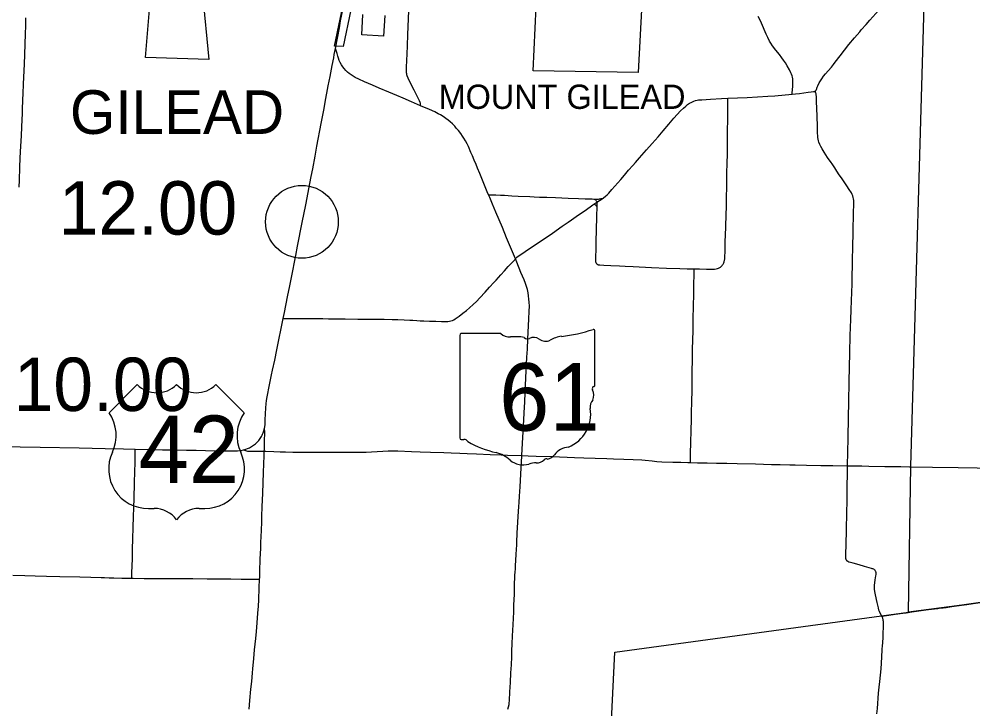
# Model space of a CAD drawing. Extents: x 1815539 to 1947826, y 273303 to 993194.
# Drawn here: x 1869978 to 1889640, y 911339 to 925558 of the extents above; entities that cross this region are included whole.
import ezdxf

# ---------------------------------------------------------------- set-up
doc = ezdxf.new("R2010")
doc.units = 0
for name, color, linetype in [('Default', 7, 'Continuous'), ('GM_X_Corporation', 7, 'Continuous'), ('GM_X_Corporation_Text', 7, 'Continuous'), ('GM_X_County_Road', 7, 'Continuous'), ('GM_X_State_Route', 7, 'Continuous'), ('GM_X_Township', 7, 'Continuous'), ('GM_X_Township_Road', 7, 'Continuous'), ('GM_X_Township_Text', 7, 'Continuous'), ('GM_X_US_Route', 7, 'Continuous'), ('PV_X_Shoulder', 7, 'Continuous'), ('SC_Shading3', 7, 'Continuous')]:
    doc.layers.add(name, color=color, linetype=linetype)

msp = doc.modelspace()

# ---------------------------------------------------------------- linework, layer by layer
at = {"layer": 'Default'}
msp.add_circle((1875809, 921379), 750, dxfattribs=at)
at = {"layer": 'GM_X_Corporation'}
for points in [[(1882818, 925881), (1882743, 924455), (1880574, 924491), (1880657, 926260)], [(1873757, 926076), (1873892, 924723), (1872581, 924769), (1872681, 925920)], [(1876816, 925750), (1876660, 924993), (1876483, 925000), (1876685, 925989)], [(1877517, 925630), (1877493, 925208), (1877045, 925233), (1877061, 925652)]]:
    msp.add_lwpolyline(points, dxfattribs=at)
at = {"layer": 'GM_X_County_Road'}
for points in [[(1878254, 923773), (1878254, 923791), (1878253, 923809), (1878251, 923824), (1878245, 923840), (1878232, 923870), (1878190, 923956), (1878123, 924092), (1878042, 924254), (1878000, 924342), (1877981, 924388), (1877972, 924412), (1877968, 924430), (1877965, 924450), (1877963, 924466), (1877962, 924499), (1877965, 924564), (1877977, 924843), (1877984, 925008), (1877992, 925238), (1878010, 925731), (1878016, 925917)], [(1875032, 916651), (1875034, 916687), (1875040, 916867), (1875045, 917030), (1875044, 917049), (1875041, 917073), (1875035, 917100), (1875033, 917111)], [(1874936, 914014), (1874938, 914048), (1874941, 914179), (1874951, 914424), (1874959, 914654), (1874965, 914769), (1874973, 915014), (1874979, 915195), (1874985, 915309), (1874992, 915506), (1875003, 915785), (1875010, 915998), (1875017, 916211), (1875023, 916392), (1875029, 916556), (1875032, 916651)], [(1880340, 916562), (1880475, 916559), (1880639, 916552), (1880967, 916540), (1881425, 916524), (1881622, 916518), (1881851, 916511), (1882097, 916501), (1882228, 916496), (1882441, 916490), (1882638, 916482), (1882818, 916474), (1882883, 916468), (1883029, 916451), (1883127, 916441), (1883226, 916434), (1883455, 916428), (1883619, 916425), (1883767, 916420), (1883819, 916419)], [(1883819, 916419), (1883963, 916415), (1884160, 916411), (1884357, 916406), (1884570, 916402), (1884783, 916396), (1885160, 916388), (1885488, 916380), (1885668, 916375), (1885864, 916371), (1885979, 916369), (1886209, 916366), (1886504, 916360), (1886750, 916358), (1887055, 916352)], [(1887765, 913249), (1887727, 913315), (1887714, 913344), (1887704, 913375), (1887691, 913422), (1887665, 913534), (1887630, 913694), (1887619, 913759), (1887613, 913807), (1887611, 913840), (1887613, 913888), (1887618, 913937), (1887628, 914002), (1887642, 914083), (1887645, 914109), (1887645, 914116), (1887646, 914123), (1887646, 914133), (1887645, 914141), (1887644, 914150), (1887642, 914158), (1887640, 914167), (1887636, 914175), (1887632, 914182), (1887627, 914190), (1887622, 914196), (1887616, 914202), (1887609, 914207), (1887602, 914212), (1887595, 914217), (1887580, 914224), (1887564, 914230), (1887548, 914235), (1887406, 914276), (1887295, 914306), (1887169, 914341), (1887090, 914365), (1887084, 914367), (1887075, 914371), (1887068, 914375), (1887061, 914378), (1887055, 914382), (1887049, 914387), (1887044, 914392), (1887038, 914398), (1887034, 914404), (1887030, 914411), (1887027, 914417), (1887024, 914426), (1887022, 914432), (1887021, 914441), (1887019, 914449), (1887019, 914457), (1887018, 914489), (1887021, 914555), (1887026, 914702), (1887028, 914801), (1887028, 914817), (1887031, 914931), (1887035, 915078), (1887039, 915341), (1887046, 915669), (1887051, 915866), (1887058, 916244), (1887055, 916352)], [(1869852, 914094), (1870098, 914088), (1870311, 914082), (1870541, 914077), (1870820, 914070), (1871230, 914060), (1871459, 914053), (1871672, 914048), (1871738, 914046), (1871836, 914044), (1871934, 914041), (1872098, 914036), (1872301, 914032)], [(1872301, 914032), (1872328, 914032), (1872557, 914029), (1872754, 914028), (1872902, 914026), (1872984, 914025), (1873164, 914026), (1873377, 914026), (1873558, 914025), (1873853, 914022), (1874083, 914021), (1874345, 914019), (1874559, 914017), (1874755, 914017), (1874903, 914015), (1874936, 914014)], [(1874719, 911335), (1874736, 911514), (1874757, 911743), (1874773, 911907), (1874789, 912086), (1874796, 912168), (1874817, 912380), (1874834, 912560), (1874858, 912788), (1874871, 912935), (1874887, 913115), (1874903, 913311), (1874912, 913459), (1874918, 913590), (1874929, 913835), (1874936, 914014)], [(1887662, 911236), (1887671, 911350), (1887696, 911661), (1887708, 911791), (1887721, 911905), (1887735, 912036), (1887746, 912166), (1887754, 912281), (1887763, 912412), (1887770, 912557), (1887777, 912655), (1887780, 912687), (1887787, 912833), (1887793, 912931), (1887797, 912996), (1887800, 913061), (1887800, 913094), (1887798, 913127), (1887795, 913144), (1887792, 913160), (1887789, 913177), (1887781, 913208), (1887777, 913221), (1887775, 913228), (1887771, 913238), (1887765, 913249)]]:
    msp.add_lwpolyline(points, dxfattribs=at)
at = {"layer": 'GM_X_State_Route'}
for points in [[(1880340, 916567), (1880381, 917295), (1880389, 917442), (1880403, 917672), (1880413, 917852), (1880427, 918163), (1880448, 918589), (1880456, 918753), (1880467, 918966), (1880489, 919375), (1880495, 919539), (1880497, 919638), (1880494, 919720), (1880489, 919786), (1880481, 919851), (1880470, 919916), (1880456, 919981), (1880443, 920028), (1880416, 920106), (1880387, 920183), (1880324, 920335), (1880238, 920547), (1880209, 920616), (1880167, 920714), (1880029, 921047), (1879940, 921259), (1879808, 921577), (1879736, 921741), (1879680, 921879), (1879656, 921938), (1879630, 922000), (1879561, 922166), (1879473, 922378), (1879428, 922484), (1879398, 922560), (1879361, 922651), (1879322, 922740), (1879316, 922754), (1879303, 922782), (1879291, 922810), (1879239, 922929), (1879212, 922988), (1879182, 923047), (1879148, 923104), (1879121, 923145), (1879083, 923198), (1879033, 923263), (1878991, 923313), (1878958, 923350), (1878911, 923396), (1878863, 923440), (1878825, 923472), (1878772, 923512), (1878718, 923549), (1878662, 923584), (1878619, 923608), (1878546, 923645), (1878441, 923693), (1878254, 923773), (1878064, 923855), (1877898, 923925), (1877763, 923984), (1877597, 924054), (1877400, 924136), (1877265, 924195), (1877100, 924266), (1876980, 924320), (1876907, 924355), (1876864, 924379), (1876823, 924406), (1876784, 924435), (1876747, 924467), (1876712, 924501), (1876680, 924538), (1876650, 924576), (1876623, 924617), (1876599, 924660), (1876579, 924704), (1876562, 924750), (1876547, 924797), (1876534, 924847), (1876499, 924955)], [(1880055, 911332), (1880068, 911380), (1880079, 911428), (1880083, 911461), (1880087, 911510), (1880095, 911690), (1880107, 911887), (1880117, 912084), (1880126, 912247), (1880133, 912411), (1880136, 912510), (1880144, 912706), (1880148, 912821), (1880156, 912985), (1880160, 913050), (1880169, 913230), (1880174, 913311), (1880177, 913377), (1880180, 913475), (1880188, 913705), (1880192, 913885), (1880193, 913934), (1880193, 913966), (1880195, 913998), (1880197, 914047), (1880200, 914096), (1880205, 914160), (1880209, 914226), (1880213, 914307), (1880218, 914388), (1880221, 914437), (1880224, 914486), (1880226, 914535), (1880231, 914616), (1880237, 914731), (1880240, 914780), (1880242, 914845), (1880245, 914894), (1880248, 914959), (1880262, 915188), (1880268, 915302), (1880281, 915511), (1880286, 915592), (1880293, 915723), (1880306, 915919), (1880320, 916181), (1880340, 916558), (1880340, 916562), (1880340, 916567)]]:
    msp.add_lwpolyline(points, dxfattribs=at)
at = {"layer": 'GM_X_Township'}
for points in [[(1889943, 913553), (1889411, 913481), (1888309, 913332), (1888362, 916340), (1888657, 926560), (1888668, 926924), (1888752, 929651), (1891412, 929604)], [(1880714, 883463), (1880836, 885744), (1880863, 886256), (1881338, 891636), (1881703, 897023), (1881803, 900282), (1881806, 900375), (1881918, 903829), (1881985, 905459), (1882074, 908232), (1882082, 908847), (1882260, 912507), (1887758, 913255), (1888309, 913332)]]:
    msp.add_lwpolyline(points, dxfattribs=at)
at = {"layer": 'GM_X_Township_Road'}
for points in [[(1887308, 925298), (1887340, 925335), (1887437, 925447), (1887512, 925533), (1887577, 925607), (1887698, 925741), (1887788, 925837), (1887856, 925908), (1887915, 925965), (1887976, 926020), (1888075, 926107), (1888135, 926162), (1888217, 926242), (1888282, 926306)], [(1869978, 922096), (1869984, 922238), (1869995, 922500), (1870004, 922697), (1870015, 922942), (1870025, 923155), (1870036, 923336), (1870043, 923483), (1870047, 923614), (1870050, 923696), (1870059, 923893), (1870065, 924024), (1870072, 924220), (1870084, 924499), (1870090, 924630), (1870095, 924827), (1870102, 925040), (1870109, 925253), (1870115, 925417), (1870120, 925581)], [(1885915, 924011), (1885916, 924031), (1885927, 924178), (1885931, 924243), (1885931, 924293), (1885928, 924326), (1885923, 924359), (1885913, 924391), (1885901, 924422), (1885887, 924452), (1885857, 924510), (1885809, 924596), (1885775, 924653), (1885739, 924708), (1885701, 924762), (1885651, 924826), (1885579, 924916), (1885509, 925007), (1885472, 925061), (1885447, 925103), (1885410, 925176), (1885376, 925250), (1885280, 925477), (1885246, 925552), (1885216, 925610)], [(1886386, 924072), (1886392, 924076), (1886398, 924081), (1886403, 924086), (1886407, 924093), (1886413, 924108), (1886429, 924154), (1886442, 924185), (1886471, 924244), (1886496, 924287), (1886523, 924328), (1886563, 924381), (1886604, 924432), (1886658, 924494), (1886723, 924568), (1886764, 924619), (1886803, 924671), (1886901, 924803), (1886992, 924920), (1887084, 925035), (1887201, 925173), (1887308, 925298)], [(1881996, 921856), (1882025, 921875), (1882064, 921905), (1882100, 921937), (1882134, 921973), (1882199, 922046), (1882383, 922255), (1882457, 922342), (1882542, 922442), (1882628, 922541), (1882682, 922602), (1882769, 922701), (1882911, 922860), (1883031, 922995), (1883151, 923130), (1883256, 923256), (1883372, 923394), (1883478, 923519), (1883544, 923593), (1883612, 923664), (1883671, 923721), (1883721, 923765), (1883759, 923796), (1883800, 923824), (1883829, 923841), (1883859, 923855), (1883889, 923868), (1883921, 923878), (1883953, 923885), (1883986, 923891), (1884052, 923897), (1884232, 923907), (1884461, 923920), (1884586, 923925)], [(1883893, 920410), (1883910, 920409), (1883933, 920409), (1884002, 920408), (1884150, 920402), (1884232, 920400), (1884281, 920401), (1884313, 920404), (1884346, 920409), (1884377, 920418), (1884393, 920423), (1884408, 920430), (1884422, 920438), (1884436, 920447), (1884448, 920457), (1884461, 920468), (1884471, 920481), (1884481, 920494), (1884490, 920508), (1884498, 920522), (1884504, 920537), (1884510, 920552), (1884515, 920568), (1884518, 920584), (1884523, 920617), (1884527, 920666), (1884530, 920764), (1884536, 920960), (1884545, 921272), (1884554, 921534), (1884558, 921681), (1884561, 921911), (1884565, 922074), (1884570, 922369), (1884574, 922599), (1884579, 922762), (1884580, 922861), (1884580, 923008), (1884583, 923238), (1884586, 923500), (1884586, 923738), (1884586, 923841), (1884586, 923893), (1884586, 923925)], [(1884586, 923925), (1884986, 923943), (1885412, 923968), (1885559, 923978), (1885915, 924011)], [(1885915, 924011), (1885984, 924017), (1886065, 924027), (1886243, 924053), (1886308, 924060), (1886357, 924064), (1886365, 924065), (1886373, 924067), (1886380, 924069), (1886386, 924072)], [(1887055, 916352), (1887062, 916636), (1887066, 916915), (1887074, 917357), (1887080, 917653), (1887090, 918095), (1887097, 918374), (1887105, 918686), (1887113, 919030), (1887119, 919210), (1887125, 919358), (1887131, 919571), (1887142, 919932), (1887148, 920096), (1887150, 920194), (1887153, 920309), (1887156, 920440), (1887158, 920538), (1887167, 920915), (1887172, 921112), (1887174, 921292), (1887178, 921456), (1887180, 921604), (1887183, 921702), (1887185, 921784), (1887183, 921817), (1887179, 921850), (1887172, 921883), (1887163, 921915), (1887151, 921945), (1887136, 921975), (1887090, 922044), (1887038, 922123), (1886983, 922205), (1886930, 922285), (1886886, 922350), (1886836, 922426), (1886794, 922489), (1886764, 922534), (1886736, 922574), (1886718, 922601), (1886644, 922708), (1886573, 922817), (1886531, 922887), (1886508, 922931), (1886486, 922975), (1886467, 923020), (1886457, 923050), (1886449, 923082), (1886444, 923114), (1886440, 923146), (1886436, 923211), (1886434, 923342), (1886429, 923555), (1886419, 923867), (1886415, 923965), (1886411, 923998), (1886407, 924014), (1886401, 924030), (1886386, 924072)], [(1879656, 921938), (1879669, 921937), (1879723, 921936), (1879805, 921933), (1879903, 921929), (1879985, 921926), (1880133, 921918), (1880264, 921911), (1880510, 921898), (1880593, 921894), (1880708, 921889), (1880856, 921885), (1881037, 921878), (1881300, 921868), (1881513, 921858), (1881645, 921854), (1881728, 921852), (1881794, 921850), (1881826, 921846), (1881833, 921846), (1881839, 921844), (1881845, 921842), (1881849, 921841)], [(1881829, 921742), (1881885, 921781)], [(1881849, 921841), (1881854, 921844), (1881857, 921845), (1881861, 921845), (1881889, 921847), (1881924, 921848), (1881942, 921851), (1881959, 921854), (1881978, 921859), (1881981, 921860), (1881983, 921860), (1881985, 921860), (1881986, 921860), (1881987, 921859), (1881990, 921859), (1881992, 921858), (1881996, 921856)], [(1881849, 921841), (1881857, 921836), (1881863, 921831), (1881868, 921824), (1881873, 921814), (1881878, 921804), (1881885, 921781)], [(1881885, 921781), (1881942, 921821), (1881996, 921856)], [(1881885, 921781), (1881886, 921749), (1881886, 921716), (1881886, 921697)], [(1880209, 920616), (1880216, 920625), (1880227, 920637), (1880240, 920649), (1880266, 920669), (1880320, 920707), (1880497, 920826), (1880619, 920908), (1880972, 921148), (1881175, 921287), (1881296, 921372), (1881363, 921419), (1881512, 921521), (1881647, 921613), (1881808, 921727), (1881829, 921742)], [(1881829, 921742), (1881848, 921733), (1881852, 921731), (1881856, 921729), (1881860, 921727), (1881864, 921724), (1881867, 921721), (1881871, 921717), (1881874, 921712), (1881886, 921697)], [(1881886, 921697), (1881881, 921487), (1881876, 921208), (1881870, 920979), (1881866, 920831), (1881859, 920634), (1881858, 920585), (1881859, 920569), (1881860, 920561), (1881862, 920553), (1881864, 920544), (1881868, 920537), (1881871, 920531), (1881876, 920523), (1881881, 920518), (1881887, 920512), (1881895, 920506), (1881901, 920503), (1881907, 920499), (1881916, 920496), (1881923, 920494), (1881932, 920493), (1881940, 920491), (1881948, 920491), (1882030, 920487), (1882177, 920480), (1882358, 920472), (1882472, 920466), (1882636, 920459), (1883013, 920440), (1883324, 920426), (1883602, 920414), (1883753, 920411), (1883864, 920410), (1883878, 920410), (1883893, 920410)], [(1875425, 919388), (1875471, 919389), (1875570, 919389), (1875750, 919387), (1875914, 919387), (1876242, 919384), (1876357, 919382), (1876538, 919380), (1876702, 919377), (1876964, 919375), (1877325, 919373), (1877506, 919371), (1877670, 919368), (1877785, 919364), (1877916, 919359), (1878031, 919354), (1878096, 919350), (1878178, 919345), (1878243, 919340), (1878325, 919336), (1878440, 919332), (1878571, 919330), (1878686, 919327), (1878784, 919324), (1878817, 919325), (1878849, 919329), (1878880, 919336), (1878910, 919347), (1878939, 919361), (1878967, 919378), (1879047, 919435), (1879126, 919494), (1879203, 919554), (1879266, 919607), (1879340, 919672), (1879410, 919740), (1879478, 919811), (1879589, 919932), (1879677, 920029), (1879766, 920126), (1879810, 920175), (1879909, 920285), (1879985, 920370), (1880062, 920455), (1880163, 920564), (1880188, 920590), (1880199, 920603), (1880209, 920616)], [(1883819, 916419), (1883819, 916454), (1883820, 916485), (1883822, 916617), (1883828, 916814), (1883834, 917092), (1883838, 917289), (1883840, 917469), (1883844, 917649), (1883850, 917928), (1883855, 918305), (1883858, 918518), (1883863, 918747), (1883871, 919140), (1883876, 919370), (1883882, 919648), (1883886, 919878), (1883890, 920074), (1883892, 920304), (1883893, 920371), (1883893, 920389), (1883893, 920402), (1883893, 920410)], [(1872301, 914032), (1872302, 914059), (1872305, 914141), (1872314, 914436), (1872318, 914633), (1872324, 914846), (1872332, 915076), (1872339, 915305), (1872343, 915486), (1872349, 915683), (1872358, 915994), (1872364, 916240), (1872368, 916404), (1872373, 916650), (1872374, 916692)], [(1874606, 916678), (1874624, 916671), (1874645, 916663), (1874663, 916659), (1874686, 916655), (1874702, 916654), (1874752, 916652), (1874867, 916651), (1875032, 916651)], [(1875032, 916651), (1875063, 916651), (1875227, 916644), (1875358, 916640), (1875473, 916637), (1875621, 916634), (1875719, 916633), (1875834, 916632), (1875998, 916631), (1876162, 916631), (1876310, 916630), (1876523, 916629), (1876769, 916629), (1876983, 916631), (1877131, 916634), (1877245, 916637), (1877360, 916642), (1877475, 916650), (1877589, 916657), (1877687, 916660), (1877786, 916658), (1878065, 916648), (1878245, 916641), (1878458, 916633), (1878737, 916622), (1878885, 916616), (1879065, 916609), (1879213, 916603), (1879409, 916596), (1879688, 916583), (1879918, 916576), (1880049, 916572), (1880340, 916562)], [(1887055, 916352), (1887168, 916351), (1887348, 916348), (1887496, 916345), (1887824, 916338), (1888152, 916333), (1888333, 916330), (1888346, 916330)], [(1888346, 916330), (1888809, 916322), (1889334, 916313), (1889728, 916306), (1890056, 916299), (1890761, 916284), (1891090, 916278), (1891124, 916277)], [(1888253, 913319), (1888267, 913321), (1888379, 913338), (1888476, 913353), (1888573, 913367), (1888670, 913380), (1888784, 913395), (1888914, 913412), (1888946, 913417), (1889027, 913425), (1889092, 913433), (1889125, 913436), (1889206, 913447), (1889303, 913462), (1889514, 913490), (1889693, 913516), (1889936, 913551), (1890001, 913559), (1890021, 913560)], [(1887765, 913249), (1887910, 913272), (1888040, 913291), (1888253, 913319)]]:
    msp.add_lwpolyline(points, dxfattribs=at)
at = {"layer": 'GM_X_US_Route'}
for points in [[(1876499, 924955), (1876580, 925375), (1876607, 925519), (1876624, 925616), (1876643, 925712), (1876694, 925991)], [(1874996, 917002), (1875007, 917028), (1875028, 917091), (1875033, 917111), (1875036, 917122), (1875042, 917154), (1875048, 917202), (1875054, 917300), (1875065, 917546), (1875071, 917628), (1875079, 917694), (1875092, 917775), (1875141, 918016), (1875184, 918225), (1875204, 918321), (1875247, 918530), (1875291, 918739), (1875425, 919388), (1875450, 919510), (1875513, 919832), (1875559, 920057), (1875593, 920235), (1875682, 920685), (1875720, 920879), (1875815, 921362), (1875889, 921732), (1876001, 922312), (1876031, 922473), (1876080, 922731), (1876119, 922940), (1876208, 923408), (1876266, 923714), (1876290, 923843), (1876353, 924181), (1876390, 924375), (1876432, 924600), (1876463, 924762), (1876476, 924828), (1876499, 924955)], [(1869771, 916746), (1870001, 916743), (1870411, 916735), (1871214, 916719), (1871756, 916706), (1872133, 916697), (1872374, 916692), (1872642, 916686), (1872937, 916681), (1873150, 916678), (1873429, 916673), (1873626, 916670), (1873823, 916667), (1874184, 916661), (1874397, 916659), (1874479, 916661), (1874544, 916666), (1874576, 916671), (1874606, 916678), (1874654, 916692), (1874685, 916704), (1874729, 916724), (1874772, 916748), (1874813, 916774), (1874851, 916804), (1874886, 916838), (1874919, 916874), (1874948, 916913), (1874974, 916954), (1874989, 916983), (1874996, 917002)]]:
    msp.add_lwpolyline(points, dxfattribs=at)
at = {"layer": 'PV_X_Shoulder'}
for p, q in [((1872413, 918023), (1871833, 917443)), ((1874618, 917443), (1874037, 918023)), ((1872645, 915471), (1872761, 915471)), ((1873689, 915471), (1873805, 915471))]:
    msp.add_line(p, q, dxfattribs=at)
for centre, radius, start, end in [((1872819, 918437), 580, 225.573, 314.427), ((1873631, 918437), 580, 225.573, 314.427), ((1871168, 916977), 812, 334.5471, 35.0009), ((1875283, 916977), 812, 144.9991, 205.4529), ((1872636, 916283), 812, 154.8319, 270.6383), ((1873814, 916283), 812, 269.3617, 25.1681), ((1872761, 914891), 580, 36.8699, 90), ((1873689, 914891), 580, 90, 143.1301)]:
    msp.add_arc(centre, radius, start, end, dxfattribs=at)
at = {"layer": 'SC_Shading3'}
for p, q in [((1879064, 919039), (1879064, 916926)), ((1879907, 919075), (1879091, 919075)), ((1881848, 918022), (1881848, 919128)), ((1881848, 918022), (1881848, 918022))]:
    msp.add_line(p, q, dxfattribs=at)
for centre, radius, start, end in [((1879096, 919043), 32.3, 98.1301, 188.1301), ((1880101, 919320), 313, 231.6195, 271.1119), ((1880205, 917889), 1123, 80.4867, 94.9883), ((1881233, 918430), 594, 97.3462, 120.7689), ((1880856, 921956), 2953, 275.8445, 288.9065), ((1881817, 919132), 31, 351.8621, 97.738), ((1880460, 919054), 90.3, 219.7921, 297.1024), ((1880592, 918810), 188, 54.4667, 119.1411), ((1880834, 919145), 226, 233.8562, 294.8282), ((1881841, 917941), 48, 107.944, 210.337), ((1881536, 917801), 288, 340.033, 23.6496), ((1881815, 918018), 33.2, 289.6038, 7.7341), ((1881959, 917559), 210, 136.8065, 186.9296), ((1881022, 917419), 739, 292.3089, 8.9858), ((1879096, 916921), 32.5, 171.9584, 258.3066), ((1879101, 917137), 248, 267.339, 280.6039), ((1879152, 916804), 89.5, 29.7484, 93.2717), ((1880282, 918702), 2132, 240.4129, 257.1985), ((1881333, 916332), 404, 94.4031, 142.5768), ((1879647, 915976), 667, 47.1842, 75.836), ((1880368, 916793), 423, 230.7004, 286.2918), ((1880644, 916635), 226, 268.777, 315.5493), ((1880848, 916430), 63.5, 65.7517, 132.6484), ((1880821, 916721), 239, 282.8732, 323.2771), ((1880613, 916062), 348, 85.6951, 111.2099)]:
    msp.add_arc(centre, radius, start, end, dxfattribs=at)

# ---------------------------------------------------------------- texts
at = {"layer": 'Default'}
for s, p in [('12.00', (1870795, 921116)), ('10.00', (1869866, 917480))]:
    msp.add_text(s, height=1100, dxfattribs=at).set_placement(p)
at = {"layer": 'GM_X_Corporation_Text'}
msp.add_text('MOUNT GILEAD', height=500, rotation=0, dxfattribs=at).set_placement((1878626, 923707))
at = {"layer": 'GM_X_Township_Text'}
msp.add_text('GILEAD', height=900, rotation=0, dxfattribs=at).set_placement((1871027, 923191))
at = {"layer": 'PV_X_Shoulder'}
msp.add_text('42', height=1392.2, dxfattribs=at).set_placement((1872442, 915993))
at = {"layer": 'SC_Shading3'}
msp.add_text('61', height=1392.2, dxfattribs=at).set_placement((1879874, 917075))

doc.saveas('drawing.dxf')
